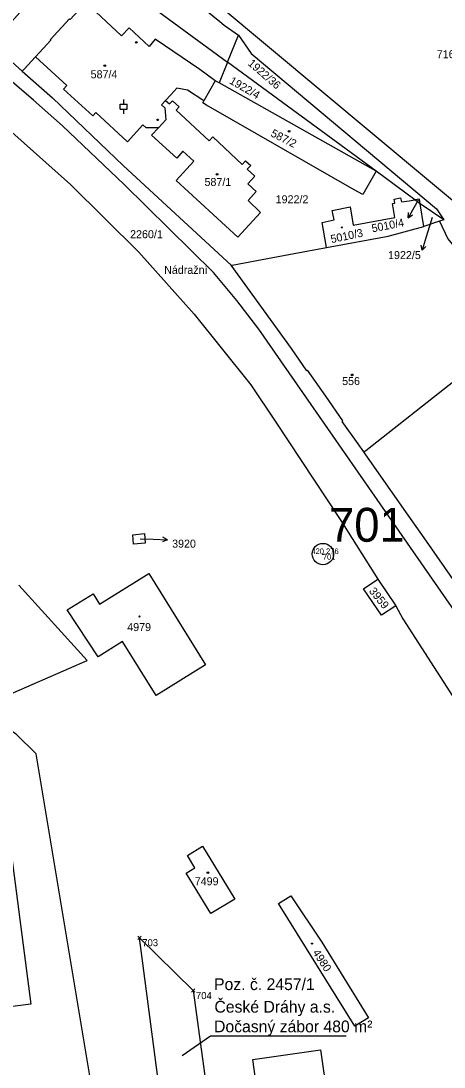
# Model space of a CAD drawing. Extents: x -667048 to -665920, y -1108425 to -1107247.
# Drawn here: x -666785.4 to -666695.6, y -1107600.6 to -1107378.4 of the extents above; entities that cross this region are included whole.
import ezdxf

# ---------------------------------------------------------------- set-up
doc = ezdxf.new("R2010")
doc.units = 0
for name, color, linetype in [('_JC - Obvod stavby - Přesunutá', 7, 'Continuous'), ('Default', 7, 'Continuous'), ('Hranice parcel', 7, 'Continuous'), ('JC - Popisky', 7, 'Continuous'), ('Parcelní čísla', 7, 'Continuous'), ('Pop_ PČ_ popisy', 7, 'Continuous'), ('RK-body obvod stavby docasny zabor', 7, 'Continuous'), ('Vrstva 1', 7, 'Continuous'), ('Vrstva 60', 7, 'Continuous'), ('Vrstva 61', 7, 'Continuous'), ('Značky budov', 7, 'Continuous'), ('Značky kultur', 7, 'Continuous')]:
    doc.layers.add(name, color=color, linetype=linetype)

# ---------------------------------------------------------------- blocks, each defined once
blk = doc.blocks.new('4.021')
at = {"layer": 'Default'}
blk.add_circle((-7, 1), 175, dxfattribs=at)
blk = doc.blocks.new('3.181')
at = {"layer": 'Default'}
for p, q in [((0, 2000), (0, 3000)), ((-750, 2000), (750, 2000)), ((-750, 1000), (-750, 2000)), ((-750, 1000), (750, 1000)), ((0, 0), (0, 1000)), ((750, 1000), (750, 2000))]:
    blk.add_line(p, q, dxfattribs=at)
blk = doc.blocks.new('10291')
at = {"layer": 'Default'}
for p, q in [((0, 3001), (-500, 2001)), ((0, 1), (0, 3001)), ((0, 3001), (500, 2001))]:
    blk.add_line(p, q, dxfattribs=at)
blk = doc.blocks.new('POINT_DISPLAY')
at = {"layer": 'Default'}
for p, q in [((-354, 354), (354, -354)), ((354, 354), (-354, -354))]:
    blk.add_line(p, q, dxfattribs=at)

msp = doc.modelspace()

# ---------------------------------------------------------------- linework, layer by layer
at = {"layer": '_JC - Obvod stavby - Přesunutá'}
msp.add_lwpolyline([(-666742.73, -1107629.44), (-666752.71, -1107630.84), (-666760.26, -1107573.13), (-666748.86, -1107584.37)], close=True, dxfattribs=at)
at = {"layer": 'Hranice parcel'}
for points in [[(-666914.82, -1107333.06), (-666908.74, -1107334.43), (-666905.84, -1107335.08), (-666891.95, -1107339.94), (-666851.81, -1107357.1), (-666830.89, -1107368.72), (-666808.07, -1107384.76), (-666792.66, -1107397.28), (-666774.87, -1107413.14), (-666760.36, -1107427.5), (-666748.63, -1107440.62), (-666736.58, -1107455.67), (-666731.43, -1107463.41), (-666717.64, -1107484.31), (-666709.65, -1107496.94)], [(-666709.89, -1107334.19), (-666696.6, -1107345.28), (-666699.63, -1107348.94), (-666645.82, -1107393.9), (-666676.68, -1107430.83), (-666743.79, -1107374.78), (-666709.89, -1107334.19)], [(-666683.99, -1107517.16), (-666734.88, -1107443.83), (-666739.56, -1107437.74), (-666744.57, -1107431.79), (-666763.51, -1107413.08), (-666776.63, -1107400.64), (-666782.75, -1107395.17), (-666793.33, -1107386.18), (-666809.9, -1107373.11), (-666816.72, -1107368.16), (-666833.93, -1107357.1), (-666840.83, -1107353.24), (-666853.59, -1107346.76), (-666868.25, -1107340.16)], [(-666790.16, -1107379.33), (-666789.77, -1107378.88), (-666788.63, -1107379.86), (-666775.94, -1107365.67), (-666771.5, -1107365.12), (-666741.55, -1107387.13)], [(-666754.01, -1107369.66), (-666743.19, -1107378.51), (-666742.27, -1107379.29), (-666739.25, -1107381.37)], [(-666744.2, -1107391.05), (-666747.45, -1107388.65), (-666756.96, -1107382.22), (-666758.21, -1107383.76), (-666762.46, -1107379.83), (-666764.1, -1107381.55), (-666771.68, -1107374.43), (-666775, -1107378.02), (-666775.11, -1107377.91), (-666779.22, -1107382.36), (-666779.1, -1107382.47), (-666782.32, -1107385.96)], [(-666741.55, -1107387.13), (-666739.25, -1107381.37)], [(-666739.25, -1107381.37), (-666736.54, -1107385.3), (-666697.16, -1107418.3), (-666695.61, -1107420.61)], [(-666785.15, -1107389.03), (-666790.17, -1107384.6)], [(-666782.32, -1107385.96), (-666784.75, -1107388.59), (-666785.15, -1107389.03)], [(-666756.23, -1107401.09), (-666758.82, -1107401.08), (-666759.52, -1107400.44), (-666762.8, -1107404.01), (-666769.5, -1107397.81), (-666770.18, -1107398.55), (-666776.37, -1107392.83), (-666775.69, -1107392.09), (-666782.32, -1107385.96)], [(-666741.55, -1107387.13), (-666743.31, -1107391.5)], [(-666710.02, -1107410.3), (-666741.55, -1107387.13)], [(-666785.15, -1107389.03), (-666778.75, -1107394.69)], [(-666744.2, -1107391.05), (-666746.58, -1107395.35)], [(-666743.31, -1107391.5), (-666744.2, -1107391.05)], [(-666710.02, -1107410.3), (-666743.31, -1107391.5)], [(-666778.75, -1107394.69), (-666763.66, -1107409.15), (-666740.76, -1107430.26)], [(-666753.57, -1107394.07), (-666754.71, -1107395.26)], [(-666746.58, -1107395.35), (-666750.06, -1107393.1), (-666752.3, -1107392.61), (-666753.57, -1107394.07)], [(-666754.71, -1107395.26), (-666753.91, -1107395.99), (-666753.27, -1107395.3), (-666751.86, -1107396.59), (-666752.5, -1107397.28), (-666745.46, -1107403.82), (-666744.68, -1107402.97), (-666738.46, -1107408.86), (-666737.74, -1107408.08), (-666736.63, -1107409.09), (-666737.36, -1107409.88), (-666735.79, -1107411.37), (-666737.23, -1107412.94), (-666735.46, -1107414.62), (-666737.18, -1107416.5), (-666734.59, -1107419.07), (-666739.4, -1107424.28), (-666752.47, -1107412.26), (-666748.7, -1107408.18), (-666751.03, -1107406.05), (-666752.35, -1107407.48), (-666757.68, -1107402.62), (-666756.23, -1107401.09)], [(-666755.59, -1107396.18), (-666754.9, -1107396.81), (-666754.68, -1107399.39), (-666756.23, -1107401.09)], [(-666754.71, -1107395.26), (-666755.59, -1107396.18)], [(-666710.02, -1107410.3), (-666712.86, -1107415.24), (-666714.64, -1107414.22), (-666746.03, -1107396.28), (-666746.82, -1107395.78), (-666746.58, -1107395.35)], [(-666701.82, -1107416.36), (-666710.02, -1107410.3)], [(-666720.52, -1107426.51), (-666721.43, -1107421.15), (-666718.95, -1107420.64), (-666719.32, -1107418.62), (-666715.54, -1107417.86), (-666714.89, -1107421.73), (-666706.03, -1107420.09), (-666706.52, -1107417.17), (-666706.05, -1107417.08), (-666706.2, -1107416.22), (-666704.8, -1107415.93), (-666704.65, -1107416.82), (-666703.02, -1107416.55), (-666701.82, -1107416.36)], [(-666700.62, -1107417.23), (-666700.78, -1107416.19), (-666701.82, -1107416.36)], [(-666700.62, -1107417.23), (-666701.82, -1107416.36)], [(-666695.61, -1107420.61), (-666700.62, -1107417.23)], [(-666699.84, -1107422.06), (-666700.62, -1107417.23)], [(-666696.52, -1107420.87), (-666699.84, -1107422.06)], [(-666695.61, -1107420.61), (-666696.52, -1107420.87)], [(-666696.52, -1107420.87), (-666694.79, -1107424.65), (-666679.98, -1107442.8)], [(-666720.52, -1107426.51), (-666707.47, -1107424.09), (-666699.84, -1107422.06)], [(-666740.76, -1107430.26), (-666740.56, -1107430.23), (-666735.34, -1107429.26), (-666727.41, -1107427.79), (-666720.52, -1107426.51)], [(-666712.63, -1107469.93), (-666713.84, -1107468.21), (-666717.21, -1107463.43), (-666717.09, -1107463.35), (-666720.69, -1107458.11), (-666724.57, -1107452.57), (-666724.71, -1107452.66), (-666727.99, -1107447.97), (-666740.76, -1107430.26)], [(-666712.63, -1107469.93), (-666712.2, -1107469.59), (-666693.13, -1107454.61)], [(-666692.63, -1107498.45), (-666699.79, -1107488.19), (-666703.18, -1107483.36), (-666710.37, -1107473.15), (-666710.49, -1107472.97), (-666712.19, -1107470.56), (-666712.63, -1107469.93)], [(-666759.2, -1107487.28), (-666759.03, -1107489.3), (-666761.53, -1107489.52), (-666761.7, -1107487.5), (-666759.2, -1107487.28)], [(-666768.75, -1107502.29), (-666758.24, -1107495.78), (-666746.21, -1107515.13), (-666756.74, -1107521.66), (-666763.83, -1107510.23), (-666769, -1107513.44), (-666775.58, -1107503.47), (-666770.12, -1107500.08), (-666768.75, -1107502.29)], [(-666705.84, -1107502.65), (-666708.88, -1107504.61), (-666712.7, -1107499.02), (-666709.65, -1107496.94)], [(-666709.65, -1107496.94), (-666705.84, -1107502.65)], [(-666794.82, -1107524.4), (-666771.36, -1107514.26), (-666785.85, -1107498.22)], [(-666705.84, -1107502.65), (-666704.35, -1107505.37), (-666693.11, -1107522.85)], [(-666750.22, -1107760.47), (-666757.71, -1107698.17), (-666769.58, -1107609.67), (-666782.23, -1107534.06), (-666786.44, -1107529.88), (-666794.82, -1107524.4)], [(-666807.05, -1107547.57), (-666788.76, -1107545.22), (-666783.3, -1107587.22), (-666819.37, -1107591.83), (-666820.87, -1107580.03), (-666822.1, -1107580.21), (-666821.75, -1107583.04), (-666833.95, -1107584.57), (-666834.72, -1107578.21), (-666835.27, -1107578.29), (-666837.07, -1107576.88), (-666837.35, -1107574.64), (-666835.94, -1107572.84), (-666835.4, -1107572.79), (-666836.94, -1107560.49), (-666824.78, -1107558.96), (-666824.42, -1107561.79), (-666823.23, -1107561.61), (-666823.98, -1107555.66), (-666806.31, -1107553.39), (-666807.05, -1107547.57)], [(-666750.31, -1107559.39), (-666748.5, -1107558.29), (-666750.09, -1107555.64), (-666746.87, -1107553.66), (-666740.03, -1107564.97), (-666745.1, -1107568.01), (-666750.31, -1107559.39)], [(-666711.61, -1107590.13), (-666714.53, -1107591.94), (-666730.71, -1107565.84), (-666728.12, -1107564.23), (-666721.55, -1107574.1), (-666711.61, -1107590.13)], [(-666732.05, -1107628.66), (-666736.22, -1107598.97), (-666721.8, -1107596.97), (-666717.54, -1107626.48)]]:
    msp.add_lwpolyline(points, dxfattribs=at)
at = {"layer": 'JC - Popisky'}
msp.add_line((-666745.2, -1107593.96), (-666744.2, -1107593.96), dxfattribs=at)
for points in [[(-666751.21, -1107598.14), (-666745.2, -1107593.96)], [(-666744.2, -1107593.96), (-666716.36, -1107593.96)]]:
    msp.add_lwpolyline(points, dxfattribs=at)
at = {"layer": 'Pop_ PČ_ popisy'}
for points in [[(-666701.1, -1107416.43), (-666701.73, -1107417.55)], [(-666698.11, -1107420.12), (-666699.35, -1107424.22)], [(-666760.08, -1107488.38), (-666757.33, -1107488.47)]]:
    msp.add_lwpolyline(points, dxfattribs=at)
at = {"layer": 'Vrstva 1'}
msp.add_line((-666721.46, -1107491.63), (-666721.16, -1107491.63), dxfattribs=at)
msp.add_circle((-666721.31, -1107491.63), 2.27, dxfattribs=at)
at = {"layer": 'Vrstva 60'}
msp.add_line((-666721.31, -1107491.63), (-666721.31, -1107491.63), dxfattribs=at)

# ---------------------------------------------------------------- block references
at = {"layer": 'Pop_ PČ_ popisy'}
for p, xscale, yscale, rotation in [((-666701.73, -1107417.55), 0.001, 0.0010000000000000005, 151.0000001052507), ((-666699.35, -1107424.22), 0.0010000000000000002, 0.0010000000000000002, 162.99999999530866), ((-666757.33, -1107488.47), 0.0010000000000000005, 0.0010000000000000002, -91.99999995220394)]:
    msp.add_blockref('10291', p, dxfattribs=dict(at, xscale=xscale, yscale=yscale, rotation=rotation))
at = {"layer": 'RK-body obvod stavby docasny zabor', "xscale": 0.0010000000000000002, "yscale": 0.0010000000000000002}
for p in [(-666760.26, -1107573.13), (-666748.86, -1107584.37)]:
    msp.add_blockref('POINT_DISPLAY', p, dxfattribs=at)
at = {"layer": 'Značky budov'}
for p, xscale, yscale in [((-666760.93, -1107382.91), 0.0010000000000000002, 0.0010000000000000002), ((-666767.62, -1107387.85), 0.0010000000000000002, 0.0010000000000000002), ((-666756.39, -1107399.37), 0.0010000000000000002, 0.0010000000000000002), ((-666728.47, -1107401.8), 0.0010000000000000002, 0.0010000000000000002), ((-666743.76, -1107410.94), 0.0010000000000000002, 0.0010000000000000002), ((-666717.28, -1107422.22), 0.0006700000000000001, 0.0006700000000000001), ((-666715.1, -1107453.56), 0.0010000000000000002, 0.0010000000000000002), ((-666760.25, -1107504.89), 0.0006700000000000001, 0.0006700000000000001), ((-666745.72, -1107559.3), 0.0010000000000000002, 0.0010000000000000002), ((-666723.61, -1107574.37), 0.0006700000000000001, 0.0006700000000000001)]:
    msp.add_blockref('4.021', p, dxfattribs=dict(at, xscale=xscale, yscale=yscale))
at = {"layer": 'Značky kultur', "xscale": 0.0010000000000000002, "yscale": 0.0010000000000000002}
msp.add_blockref('3.181', (-666763.61, -1107398.07), dxfattribs=at)

# ---------------------------------------------------------------- texts
at = {"layer": 'JC - Popisky'}
for s, p in [('Poz. č. 2457/1', (-666744.42, -1107584.25)), ('České Dráhy a.s.', (-666744.34, -1107589.04)), ('Dočasný zábor 480 m²', (-666744.42, -1107593.22))]:
    msp.add_text(s, height=2.5, dxfattribs=at).set_placement(p)
at = {"layer": 'Parcelní čísla'}
for s, p in [('7165', (-666697.13, -1107386.27)), ('587/4', (-666770.63, -1107390.54)), ('587/1', (-666746.45, -1107413.42)), ('1922/2', (-666731.34, -1107417.1)), ('2260/1', (-666762.25, -1107424.52)), ('1922/5', (-666707.47, -1107428.95)), ('556', (-666717.23, -1107455.72)), ('3920', (-666753.33, -1107490.26)), ('4979', (-666762.86, -1107507.98)), ('7499', (-666748.52, -1107561.98))]:
    msp.add_text(s, height=1.7, dxfattribs=at).set_placement(p)
for s, rotation, p in [('1922/36', 319, (-666737.38, -1107387.59)), ('1922/4', 330, (-666741.32, -1107391.55)), ('587/2', 333, (-666732.54, -1107402.77)), ('5010/4', 11, (-666710.79, -1107423.29)), ('5010/3', 12, (-666719.48, -1107425.58)), ('3959', 309, (-666711.62, -1107499.53)), ('4980', 303, (-666723.56, -1107576.3))]:
    msp.add_text(s, height=1.7, rotation=rotation, dxfattribs=at).set_placement(p)
at = {"layer": 'Pop_ PČ_ popisy'}
msp.add_text('Nádražní', height=1.7, dxfattribs=at).set_placement((-666755.02, -1107432.09))
at = {"layer": 'RK-body obvod stavby docasny zabor'}
for s, p in [('703', (-666759.66, -1107574.93)), ('704', (-666748.26, -1107586.17))]:
    msp.add_text(s, height=1.5, dxfattribs=at).set_placement(p)
at = {"layer": 'Vrstva 1'}
msp.add_text('701', height=7.2, dxfattribs=at).set_placement((-666720, -1107489))
at = {"layer": 'Vrstva 60'}
msp.add_text('701', height=1.2, dxfattribs=at).set_placement((-666721.31, -1107492.83))
at = {"layer": 'Vrstva 61'}
msp.add_text('420.276', height=1.2, dxfattribs=at).set_placement((-666723.76, -1107491.63))

doc.saveas('drawing.dxf')
